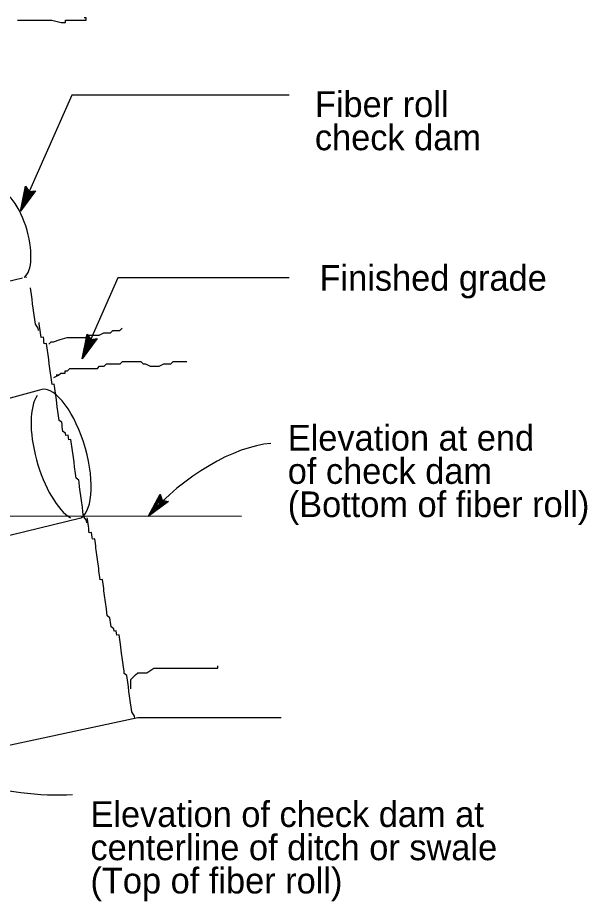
# Model space of a CAD drawing. Extents: x 6707415 to 6708768, y 1869893 to 1870831.
# Drawn here: x 6707891.3 to 6708024.3, y 1870144.6 to 1870351.9 of the extents above; entities that cross this region are included whole.
import ezdxf

# ---------------------------------------------------------------- set-up
doc = ezdxf.new("R2010")
doc.units = 0
for name, color, linetype in [('56 Stg 3 Anno', 7, 'Continuous'), ('57 Undefined', 7, 'Continuous'), ('60 Nongeo Data', 7, 'Continuous')]:
    doc.layers.add(name, color=color, linetype=linetype)

msp = doc.modelspace()

# ---------------------------------------------------------------- linework, layer by layer
at = {"layer": '56 Stg 3 Anno'}
for p, q in [((6707903.94, 1870333.87), (6707892, 1870306.77)), ((6707954.76, 1870333.87), (6707903.94, 1870333.87)), ((6707892, 1870306.77), (6707893.15, 1870312.55)), ((6707892.53, 1870307.99), (6707893.37, 1870312.21)), ((6707893.15, 1870312.55), (6707893.15, 1870312.55)), ((6707893.15, 1870312.55), (6707894.01, 1870311.34)), ((6707895.5, 1870311.52), (6707892, 1870306.77)), ((6707895.1, 1870311.47), (6707892.53, 1870307.98)), ((6707893.07, 1870309.19), (6707893.61, 1870311.92)), ((6707894.69, 1870311.4), (6707893.07, 1870309.19)), ((6707893.6, 1870310.41), (6707893.84, 1870311.57)), ((6707894.32, 1870311.38), (6707893.6, 1870310.41)), ((6707894.01, 1870311.34), (6707895.5, 1870311.52)), ((6707895.5, 1870311.52), (6707895.5, 1870311.52)), ((6707892, 1870306.77), (6707892, 1870306.77)), ((6707914.72, 1870291.16), (6707906.38, 1870272.22)), ((6707954.76, 1870291.15), (6707914.72, 1870291.16)), ((6707906.38, 1870272.22), (6707907.53, 1870278)), ((6707909.87, 1870276.97), (6707906.38, 1870272.22)), ((6707906.91, 1870273.44), (6707907.75, 1870277.66)), ((6707907.45, 1870274.64), (6707907.99, 1870277.37)), ((6707907.53, 1870278), (6707907.53, 1870278)), ((6707907.53, 1870278), (6707908.39, 1870276.79)), ((6707907.98, 1870275.86), (6707908.21, 1870277.02)), ((6707908.39, 1870276.79), (6707909.87, 1870276.97)), ((6707909.87, 1870276.97), (6707909.87, 1870276.97)), ((6707909.48, 1870276.92), (6707906.91, 1870273.43)), ((6707909.07, 1870276.85), (6707907.45, 1870274.64)), ((6707908.7, 1870276.83), (6707907.98, 1870275.86)), ((6707906.38, 1870272.22), (6707906.38, 1870272.22)), ((6707921.77, 1870235.44), (6707924.6, 1870240.62)), ((6707922.65, 1870236.45), (6707924.72, 1870240.22)), ((6707923.52, 1870237.44), (6707924.85, 1870239.87)), ((6707924.6, 1870240.62), (6707924.6, 1870240.62)), ((6707924.6, 1870240.62), (6707925.06, 1870239.2)), ((6707926.53, 1870238.93), (6707921.77, 1870235.44)), ((6707926.14, 1870239), (6707922.64, 1870236.44)), ((6707925.73, 1870239.06), (6707923.52, 1870237.44)), ((6707924.39, 1870238.43), (6707924.96, 1870239.48)), ((6707925.37, 1870239.15), (6707924.39, 1870238.43)), ((6707925.06, 1870239.2), (6707926.53, 1870238.93)), ((6707926.53, 1870238.93), (6707926.53, 1870238.93)), ((6707943.59, 1870235.44), (6707754.24, 1870235.45)), ((6707921.77, 1870235.44), (6707921.77, 1870235.44))]:
    msp.add_line(p, q, dxfattribs=at)
for centre, major_axis, ratio, start_param, end_param in [((6707936.47, 1870232.34), (-21.36, -17.68), 0.450502, 3.694848, 5.056238), ((6707855.02, 1870222.1), (68.84, -42.22), 0.434429, 4.031868, 5.732815)]:
    msp.add_ellipse(centre, major_axis=major_axis, ratio=ratio, start_param=start_param, end_param=end_param, dxfattribs=at)
at = {"layer": '60 Nongeo Data'}
for p, q in [((6707854.3, 1870282.12), (6707892.42, 1870291.13)), ((6707893.26, 1870291.31), (6707893.39, 1870291.33)), ((6707773.47, 1870202.47), (6707906.05, 1870235.11)), ((6707919.37, 1870188.45), (6707952.86, 1870188.45))]:
    msp.add_line(p, q, dxfattribs=at)
for points in [[(6707891.29, 1870351.4), (6707891.83, 1870351.4), (6707892.36, 1870351.4), (6707892.9, 1870351.4), (6707893.43, 1870351.4), (6707893.97, 1870351.4), (6707894.5, 1870351.4), (6707895.04, 1870351.4), (6707895.57, 1870351.4), (6707896.65, 1870351.4), (6707897.72, 1870351.4), (6707898.79, 1870351.4), (6707899.32, 1870351.4), (6707901.46, 1870350.86), (6707902.53, 1870350.86), (6707902.53, 1870351.4), (6707903.6, 1870351.4), (6707904.14, 1870351.4), (6707904.67, 1870351.4), (6707905.21, 1870351.4), (6707905.74, 1870351.4), (6707906.28, 1870351.4), (6707906.82, 1870351.4), (6707906.82, 1870351.4), (6707907.35, 1870351.4), (6707907.35, 1870351.93), (6707906.82, 1870351.93)], [(6707896.2, 1870278.85), (6707896.13, 1870279.38), (6707895.46, 1870280.37), (6707895.32, 1870281.42), (6707895.17, 1870282.48), (6707894.96, 1870284.07), (6707894.82, 1870285.13), (6707894.68, 1870286.19), (6707894.61, 1870286.72), (6707894.54, 1870287.25), (6707894.39, 1870288.31), (6707894.32, 1870288.84)], [(6707907.45, 1870233.93), (6707907.38, 1870234.46), (6707906.71, 1870235.45), (6707906.57, 1870236.51), (6707906.43, 1870237.57), (6707906.21, 1870239.16), (6707906.07, 1870240.22), (6707905.93, 1870241.27), (6707905.86, 1870241.8), (6707905.79, 1870242.33), (6707905.65, 1870243.39), (6707905.58, 1870243.92), (6707904.97, 1870244.38), (6707904.9, 1870244.91), (6707904.76, 1870245.97), (6707904.69, 1870246.5), (6707904.62, 1870247.03), (6707904.48, 1870248.09), (6707904.34, 1870249.15), (6707904.05, 1870251.27), (6707903.98, 1870251.8), (6707903.91, 1870252.33), (6707903.84, 1870252.86), (6707903.77, 1870253.39), (6707903.24, 1870253.32), (6707903.17, 1870253.85), (6707903.1, 1870254.38), (6707902.57, 1870254.31), (6707902.5, 1870254.84), (6707901.89, 1870255.29), (6707901.82, 1870255.82), (6707901.75, 1870256.35), (6707901.68, 1870256.88), (6707901.61, 1870257.41), (6707901.01, 1870257.87), (6707900.8, 1870259.46), (6707900.58, 1870261.05), (6707900.37, 1870262.64), (6707900.3, 1870263.17), (6707900.23, 1870263.7), (6707900.16, 1870264.23), (6707900.09, 1870264.76), (6707899.95, 1870265.82), (6707899.88, 1870266.35), (6707899.35, 1870266.28), (6707899.27, 1870266.81), (6707899.2, 1870267.34), (6707899.13, 1870267.87), (6707899.06, 1870268.4), (6707898.99, 1870268.93), (6707898.71, 1870271.05), (6707898.57, 1870272.11), (6707898.5, 1870272.64), (6707898.42, 1870273.17), (6707898.35, 1870273.69), (6707898.28, 1870274.22), (6707898.21, 1870274.75), (6707898.14, 1870275.28), (6707898.07, 1870275.81), (6707897.54, 1870275.74), (6707897.47, 1870276.27), (6707897.4, 1870276.8), (6707897.33, 1870277.33), (6707896.8, 1870277.26), (6707896.73, 1870277.79), (6707896.66, 1870278.32), (6707896.58, 1870278.85), (6707896.51, 1870279.38), (6707896.44, 1870279.91), (6707896.37, 1870280.44), (6707896.33, 1870280.76)], [(6707898.59, 1870275.66), (6707899.12, 1870276.19), (6707899.66, 1870276.19), (6707901.26, 1870276.73), (6707902.87, 1870277.26), (6707903.41, 1870277.26), (6707903.94, 1870277.26), (6707904.48, 1870277.26), (6707905.55, 1870277.26), (6707906.08, 1870277.26), (6707907.15, 1870277.26), (6707907.69, 1870277.8), (6707908.76, 1870277.8), (6707909.29, 1870277.8), (6707910.36, 1870277.8), (6707911.43, 1870278.33), (6707913.04, 1870278.33), (6707913.58, 1870278.87), (6707914.11, 1870278.87), (6707914.65, 1870278.87), (6707915.18, 1870278.87), (6707915.18, 1870278.87), (6707915.72, 1870279.4)], [(6707899.77, 1870267.85), (6707900.84, 1870268.39), (6707900.3, 1870268.39), (6707900.84, 1870268.39), (6707901.37, 1870268.92), (6707901.91, 1870268.92), (6707902.44, 1870268.92), (6707902.44, 1870269.46), (6707902.98, 1870269.46), (6707903.52, 1870269.99), (6707904.05, 1870269.99), (6707905.12, 1870269.99), (6707906.73, 1870269.99), (6707907.26, 1870269.99), (6707907.8, 1870269.99), (6707908.87, 1870269.99), (6707909.4, 1870269.99), (6707909.94, 1870269.99), (6707910.47, 1870270.52), (6707911.01, 1870270.52), (6707911.54, 1870270.52), (6707912.08, 1870271.06), (6707913.15, 1870271.06), (6707914.22, 1870271.06), (6707915.29, 1870271.06), (6707915.83, 1870271.59), (6707916.9, 1870271.59), (6707917.43, 1870271.59), (6707918.5, 1870271.59), (6707919.57, 1870271.59), (6707920.11, 1870271.59), (6707920.64, 1870271.06), (6707921.18, 1870271.06), (6707922.25, 1870270.52), (6707922.78, 1870270.52), (6707923.32, 1870270.52), (6707924.39, 1870270.52), (6707925.46, 1870271.06), (6707926, 1870271.06), (6707927.07, 1870271.06), (6707927.6, 1870271.59), (6707928.14, 1870271.59), (6707928.67, 1870271.59), (6707929.74, 1870271.59), (6707930.28, 1870271.59), (6707930.81, 1870271.59), (6707930.81, 1870271.59)], [(6707896.4, 1870264.92), (6707767.96, 1870229.96)], [(6707918.7, 1870188.26), (6707918.63, 1870188.79), (6707917.96, 1870189.78), (6707917.82, 1870190.84), (6707917.68, 1870191.9), (6707917.47, 1870193.49), (6707917.32, 1870194.55), (6707917.18, 1870195.61), (6707917.11, 1870196.14), (6707917.04, 1870196.67), (6707916.9, 1870197.73), (6707916.83, 1870198.26), (6707916.23, 1870198.72), (6707916.16, 1870199.25), (6707916.01, 1870200.31), (6707915.94, 1870200.84), (6707915.87, 1870201.36), (6707915.73, 1870202.42), (6707915.59, 1870203.48), (6707915.31, 1870205.6), (6707915.23, 1870206.13), (6707915.16, 1870206.66), (6707915.09, 1870207.19), (6707915.02, 1870207.72), (6707914.49, 1870207.65), (6707914.42, 1870208.18), (6707914.35, 1870208.71), (6707913.82, 1870208.64), (6707913.75, 1870209.17), (6707913.15, 1870209.63), (6707913.08, 1870210.16), (6707913.01, 1870210.69), (6707912.93, 1870211.22), (6707912.86, 1870211.75), (6707912.26, 1870212.21), (6707912.05, 1870213.8), (6707911.84, 1870215.38), (6707911.62, 1870216.97), (6707911.55, 1870217.5), (6707911.48, 1870218.03), (6707911.41, 1870218.56), (6707911.34, 1870219.09), (6707911.2, 1870220.15), (6707911.13, 1870220.68), (6707910.6, 1870220.61), (6707910.53, 1870221.14), (6707910.46, 1870221.67), (6707910.39, 1870222.2), (6707910.31, 1870222.73), (6707910.24, 1870223.26), (6707909.96, 1870225.38), (6707909.82, 1870226.44), (6707909.75, 1870226.97), (6707909.68, 1870227.5), (6707909.61, 1870228.03), (6707909.54, 1870228.56), (6707909.46, 1870229.09), (6707909.39, 1870229.62), (6707909.32, 1870230.15), (6707908.79, 1870230.08), (6707908.72, 1870230.61), (6707908.65, 1870231.14), (6707908.58, 1870231.67), (6707908.05, 1870231.59), (6707907.98, 1870232.12), (6707907.91, 1870232.65), (6707907.84, 1870233.18), (6707907.76, 1870233.71), (6707907.69, 1870234.24), (6707907.62, 1870234.77), (6707907.58, 1870235.09)], [(6707917.76, 1870195.17), (6707917.76, 1870197.3), (6707918.83, 1870198.37), (6707919.37, 1870198.91), (6707920.98, 1870198.91), (6707921.51, 1870198.91), (6707923.12, 1870199.98), (6707923.65, 1870199.98), (6707924.72, 1870199.98), (6707925.26, 1870199.98), (6707926.33, 1870199.98), (6707926.86, 1870199.98), (6707927.4, 1870199.98), (6707927.93, 1870199.98), (6707928.47, 1870199.98), (6707929.54, 1870199.98), (6707930.61, 1870199.98), (6707931.68, 1870199.98), (6707932.75, 1870199.98), (6707933.29, 1870199.98), (6707934.89, 1870199.98), (6707935.43, 1870199.98), (6707936.5, 1870199.98), (6707937.03, 1870199.98), (6707937.57, 1870199.98), (6707938.1, 1870199.98), (6707938.1, 1870199.98), (6707938.1, 1870200.51)], [(6707715.19, 1870144.57), (6707919.37, 1870188.45)]]:
    msp.add_lwpolyline(points, dxfattribs=at)
for centre, major_axis, start_param, end_param in [((6707889.43, 1870301.33), (-2.99, 10.2), 3.24529, 6.331966), ((6707901.11, 1870249.94), (-4.42, 15.09), 3.24529, 6.331966), ((6707901.84, 1870249.71), (-4.42, 15.09), 0.295282, 2.754116)]:
    msp.add_ellipse(centre, major_axis=major_axis, ratio=0.392736, start_param=start_param, end_param=end_param, dxfattribs=at)

# ---------------------------------------------------------------- texts
at = {"layer": '57 Undefined'}
for s, p in [('Fiber roll ', (6707960.74, 1870328.75)), ('check dam', (6707960.74, 1870320.98)), ('Finished grade', (6707961.82, 1870288.15)), ('Elevation at end', (6707954.4, 1870250.79)), ('of check dam', (6707954.4, 1870243.03)), ('(Bottom of fiber roll)', (6707954.4, 1870235.26)), ('Elevation of check dam at', (6707908.32, 1870162.86)), ('centerline of ditch or swale', (6707908.32, 1870155.1)), ('(Top of fiber roll)', (6707908.32, 1870147.33))]:
    msp.add_text(s, height=6, dxfattribs=at).set_placement(p)

doc.saveas('drawing.dxf')
